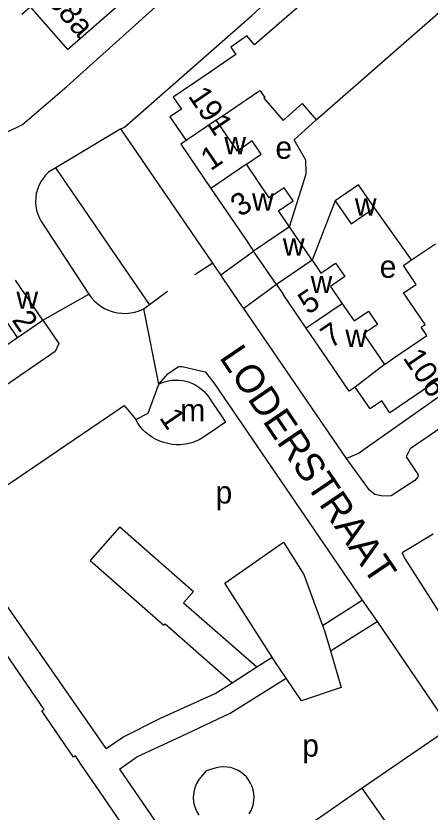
# Model space of a CAD drawing. Extents: x 157569 to 159501, y 382907 to 384670.
# Drawn here: x 158323.4 to 158397.1, y 383704.3 to 383846.2 of the extents above; entities that cross this region are included whole.
import ezdxf

# ---------------------------------------------------------------- set-up
doc = ezdxf.new("R2010")
doc.units = 0
for name, color, linetype in [('BLT_Basislijn', 7, 'Continuous'), ('BLT_Bebouwing', 7, 'Continuous'), ('BLT_Centroide', 7, 'Continuous'), ('BLT_Huisnummer', 7, 'Continuous'), ('BLT_Huisnummer_reeks', 7, 'Continuous'), ('BLT_Onderdoorgang_en_onderverdeling', 7, 'Continuous'), ('BLT_Onderverdeling_panden', 7, 'Continuous'), ('BLT_Straatnaam', 7, 'Continuous'), ('BLT_Vlakafsluiter', 7, 'Continuous')]:
    doc.layers.add(name, color=color, linetype=linetype)

msp = doc.modelspace()

# ---------------------------------------------------------------- linework, layer by layer
at = {"layer": 'BLT_Basislijn'}
for p, q in [((158342.01, 383826.07), (158330.45, 383819.11)), ((158358.4, 383802.12), (158342.01, 383826.07)), ((158330.45, 383819.11), (158329.18, 383818.35)), ((158347.17, 383794.77), (158330.45, 383819.11)), ((158380.22, 383813.28), (158376.1, 383802.66)), ((158393.82, 383802.71), (158387.19, 383811.98)), ((158327.8, 383809.68), (158336.34, 383796.6)), ((158359.82, 383800.05), (158365.69, 383804.29)), ((158358.4, 383802.12), (158355.19, 383800.04)), ((158359.82, 383800.05), (158358.4, 383802.12)), ((158347.17, 383794.77), (158350.37, 383797.15)), ((158369.75, 383798.33), (158363.92, 383794.07)), ((158346.11, 383793.98), (158347.17, 383794.77)), ((158382.24, 383767.34), (158363.92, 383794.07)), ((158339.42, 383715.64), (158311.57, 383755.66)), ((158341.86, 383755.14), (158336.58, 383749.12)), ((158341.86, 383755.14), (158354.97, 383743.62)), ((158336.58, 383749.12), (158349.69, 383737.6)), ((158353.21, 383741.61), (158354.97, 383743.62)), ((158377.93, 383737.58), (158385.04, 383742.09)), ((158385.04, 383742.09), (158387.66, 383738.25)), ((158353.21, 383741.61), (158366.25, 383730.16)), ((158349.69, 383737.6), (158349.91, 383737.85)), ((158349.91, 383737.85), (158361.85, 383727.36)), ((158377.93, 383737.58), (158378.35, 383736.41)), ((158379.35, 383733.05), (158387.66, 383738.25)), ((158387.66, 383738.25), (158400.59, 383719.26)), ((158378.35, 383736.41), (158379.35, 383733.05)), ((158369.47, 383731.13), (158368.98, 383731.89)), ((158371.48, 383728.14), (158369.47, 383731.13)), ((158400.59, 383719.26), (158385.02, 383708.53)), ((158341.8, 383711.96), (158357.3, 383689.41)), ((158385.02, 383708.53), (158357.3, 383689.41)), ((158389.91, 383701.54), (158385.02, 383708.53))]:
    msp.add_line(p, q, dxfattribs=at)
for points in [[(158342.01, 383826.07), (158342.71, 383826.37), (158365.34, 383846.3), (158395.28, 383873.99)], [(158318.74, 383825.56), (158321.24, 383825.28), (158324.51, 383826.85), (158332.42, 383833.63), (158365.06, 383863.02)], [(158372.05, 383808.62), (158375.06, 383818.05), (158374.97, 383820.5), (158372.9, 383824.11), (158376.82, 383827.72)], [(158329.18, 383818.35), (158328.65, 383817.83), (158328.18, 383817.25), (158327.78, 383816.63), (158327.44, 383815.96), (158327.18, 383815.26), (158326.99, 383814.54), (158326.89, 383813.81), (158326.86, 383813.06), (158326.91, 383812.32), (158327.04, 383811.59), (158327.25, 383810.87), (158327.54, 383810.18), (158327.8, 383809.68)], [(158447.4, 383814.83), (158445.1, 383812.79), (158444.97, 383810.48), (158443.72, 383809.2), (158403.65, 383781.83), (158384.34, 383768.23), (158382.24, 383767.34)], [(158445, 383801.93), (158445.32, 383799.37), (158444.41, 383798.79), (158442.06, 383797.45), (158441.26, 383797.32), (158439.12, 383800.11), (158438.87, 383800.08), (158393.56, 383769.02), (158392.87, 383767.64), (158395.01, 383764.4), (158394.93, 383764.04), (158394.38, 383763.41), (158390.15, 383760.66), (158388.71, 383760.59), (158387.28, 383760.91), (158386.32, 383761.7), (158382.24, 383767.34)], [(158363.92, 383794.07), (158363.71, 383794.37), (158360.37, 383799.23), (158359.82, 383800.05)], [(158336.34, 383796.6), (158336.8, 383795.97), (158337.33, 383795.39), (158337.92, 383794.87), (158338.55, 383794.42), (158339.23, 383794.03), (158339.95, 383793.71), (158340.69, 383793.46), (158341.45, 383793.29), (158342.23, 383793.21), (158343.01, 383793.2), (158343.79, 383793.27), (158344.56, 383793.42), (158345.31, 383793.64), (158346.11, 383793.98)], [(158328.13, 383792), (158330.99, 383787.84), (158330.33, 383786.41), (158289.3, 383758.13), (158285.06, 383755.48), (158281.93, 383759.97), (158277.08, 383767.05), (158268.12, 383779.99), (158267.93, 383780.28)], [(158348.79, 383780.59), (158350.39, 383782.44), (158352.33, 383783.75), (158352.94, 383783.74), (158357.03, 383782.8), (158358.62, 383780.8), (158385.04, 383742.09)], [(158311.57, 383755.66), (158342.66, 383776.75), (158344.68, 383774.25)], [(158397.67, 383753.82), (158392.13, 383750.53), (158392.52, 383749.58), (158399.52, 383738.7), (158403.73, 383732.87), (158405.96, 383732.39), (158409.36, 383734.66)], [(158368.98, 383731.89), (158360.55, 383745.11), (158370.98, 383752.4)], [(158370.98, 383752.4), (158374.64, 383746.63), (158377.93, 383737.58)], [(158366.25, 383730.16), (158368.98, 383731.89)], [(158379.35, 383733.05), (158381.28, 383726.53), (158374.19, 383724.12), (158371.48, 383728.14)], [(158361.85, 383727.36), (158366.25, 383730.16)], [(158352.82, 383717.85), (158361.5, 383721.91), (158371.48, 383728.14)], [(158339.42, 383715.64), (158342.39, 383717.66), (158348.97, 383721), (158358.85, 383725.46), (158361.85, 383727.36)], [(158341.8, 383711.96), (158344.87, 383714.13), (158352.82, 383717.85)], [(158365.77, 383706.94), (158365.73, 383707.6), (158365.61, 383708.25), (158365.41, 383708.88), (158365.14, 383709.47), (158364.8, 383710.04), (158364.39, 383710.55), (158363.93, 383711.02), (158363.4, 383711.42), (158362.84, 383711.76), (158362.24, 383712.02), (158361.61, 383712.22), (158360.96, 383712.33), (158360.3, 383712.36), (158359.65, 383712.32), (158359, 383712.19), (158357.24, 383711.62)], [(158357.24, 383711.62), (158356.24, 383710.48), (158355.85, 383709.96), (158355.51, 383709.39), (158355.25, 383708.79), (158355.07, 383708.16), (158354.96, 383707.51), (158354.93, 383706.85), (158354.98, 383706.19), (158355.11, 383705.55), (158355.32, 383704.92), (158355.6, 383704.33), (158355.95, 383703.77)], [(158364.9, 383704), (158365.23, 383704.58), (158365.48, 383705.18), (158365.65, 383705.82), (158365.75, 383706.47), (158365.77, 383706.94)]]:
    msp.add_lwpolyline(points, dxfattribs=at)
at = {"layer": 'BLT_Bebouwing'}
for p, q in [((158376.82, 383827.72), (158407.11, 383854.22)), ((158364.47, 383842.64), (158361.61, 383840.67)), ((158361.37, 383829.25), (158366.79, 383832.94)), ((158374.32, 383830.58), (158376.82, 383827.72)), ((158359.02, 383827.65), (158361.37, 383829.25)), ((158353.65, 383823.99), (158352.7, 383823.34)), ((158352.7, 383823.34), (158358.07, 383815.47)), ((158358.07, 383815.47), (158363.75, 383807.12)), ((158376.1, 383802.66), (158372.05, 383808.62)), ((158369.75, 383798.33), (158365.69, 383804.29)), ((158393.82, 383802.71), (158398.05, 383805.59)), ((158376.1, 383802.66), (158377.37, 383800.81)), ((158328.13, 383792), (158323.28, 383799.09)), ((158369.75, 383798.33), (158371.02, 383796.48)), ((158375.06, 383790.55), (158371.02, 383796.48)), ((158396.24, 383791.21), (158393.56, 383795.14)), ((158323.62, 383788.92), (158328.13, 383792)), ((158378.78, 383785.1), (158375.06, 383790.55)), ((158319.11, 383785.84), (158323.62, 383788.92)), ((158385.27, 383789.53), (158388.97, 383784.1)), ((158390.41, 383785.08), (158396.53, 383789.26)), ((158388.97, 383784.1), (158390.41, 383785.08)), ((158337.59, 383708.98), (158335.06, 383712.68))]:
    msp.add_line(p, q, dxfattribs=at)
for points in [[(158324.42, 383846.54), (158325.91, 383847.84), (158332.56, 383840.24), (158360.35, 383864.6)], [(158378.22, 383851.88), (158365.85, 383841.06), (158364.47, 383842.64)], [(158361.61, 383840.67), (158362.54, 383839.32), (158357.06, 383835.59)], [(158357.06, 383835.59), (158351.37, 383831.72), (158352.82, 383829.6), (158350.78, 383828.21), (158353.65, 383823.99)], [(158366.79, 383832.94), (158367.67, 383831.66), (158367.49, 383831.53), (158370.93, 383827.6), (158374.32, 383830.58)], [(158364.39, 383819.77), (158367.05, 383821.58), (158365.44, 383823.93), (158362.79, 383822.13), (158359.02, 383827.65)], [(158370.11, 383811.46), (158372.74, 383813.24), (158371.14, 383815.59), (158368.48, 383813.78), (158364.39, 383819.77)], [(158387.19, 383811.98), (158384.37, 383816.11), (158380.22, 383813.28)], [(158380.22, 383813.28), (158383.04, 383809.15), (158387.19, 383811.98)], [(158372.05, 383808.62), (158370.4, 383811.04), (158370.11, 383811.46)], [(158363.75, 383807.12), (158364.04, 383806.71), (158365.69, 383804.29)], [(158377.37, 383800.81), (158377.66, 383800.37), (158380.29, 383802.16), (158381.94, 383799.75), (158379.36, 383797.99), (158381.46, 383794.92)], [(158393.56, 383795.14), (158392.4, 383796.84), (158394.65, 383798.37), (158392.37, 383801.72), (158393.82, 383802.71)], [(158381.46, 383794.92), (158383.56, 383791.84), (158386.14, 383793.6), (158387.76, 383791.23), (158385.27, 383789.53)], [(158396.53, 383789.26), (158395.53, 383790.73), (158396.24, 383791.21)], [(158383.75, 383780.05), (158382.71, 383779.34), (158378.78, 383785.1)], [(158400.49, 383784.46), (158401.31, 383783.25), (158394.73, 383778.76)], [(158348.79, 383780.59), (158349.29, 383780.81), (158349.88, 383781.02), (158350.49, 383781.17), (158351.12, 383781.27), (158351.75, 383781.31), (158352.38, 383781.29), (158353.01, 383781.22), (158353.38, 383781.15), (158353.62, 383781.09), (158354.23, 383780.91), (158354.82, 383780.68), (158355.38, 383780.39), (158355.91, 383780.05), (158356.41, 383779.67), (158356.88, 383779.24), (158357.31, 383778.78), (158357.69, 383778.28), (158358.48, 383777.08), (158359.88, 383774.97), (158360.66, 383773.79), (158359.36, 383772.9), (158358.98, 383772.64), (158356.96, 383771.26), (158356.75, 383771.11), (158355.98, 383770.67), (158355.57, 383770.47), (158354.87, 383770.2), (158354.14, 383770), (158353.48, 383769.87), (158352.65, 383769.78), (158351.9, 383769.78), (158351.15, 383769.84), (158350.4, 383769.97), (158349.67, 383770.16), (158348.96, 383770.42), (158348.33, 383770.7), (158347.68, 383771.06), (158347.07, 383771.47), (158346.5, 383771.93), (158345.97, 383772.45), (158345.49, 383773.01), (158345.06, 383773.61), (158344.68, 383774.25)], [(158344.68, 383774.25), (158346.89, 383775.42), (158348.79, 383780.59)], [(158394.73, 383778.76), (158389.93, 383775.49), (158388.5, 383777.58), (158386.41, 383776.15), (158383.75, 383780.05)], [(158335.06, 383712.68), (158333.94, 383714.31), (158333.61, 383714.09), (158327.97, 383722.32), (158328.37, 383722.6), (158321.55, 383732.57)], [(158342.99, 383701.1), (158337.59, 383708.98)]]:
    msp.add_lwpolyline(points, dxfattribs=at)
at = {"layer": 'BLT_Onderdoorgang_en_onderverdeling'}
for p, q in [((158372.05, 383808.62), (158365.69, 383804.29)), ((158376.1, 383802.66), (158369.75, 383798.33))]:
    msp.add_line(p, q, dxfattribs=at)
at = {"layer": 'BLT_Onderverdeling_panden'}
for p, q in [((158359.02, 383827.65), (158353.65, 383823.99)), ((158364.39, 383819.77), (158358.07, 383815.47)), ((158323.62, 383788.92), (158318.78, 383796.01)), ((158381.46, 383794.92), (158375.06, 383790.55)), ((158388.97, 383784.1), (158383.75, 383780.05))]:
    msp.add_line(p, q, dxfattribs=at)
at = {"layer": 'BLT_Vlakafsluiter'}
for p, q in [((158328.13, 383792), (158336.34, 383796.6)), ((158348.79, 383780.59), (158346.11, 383793.98))]:
    msp.add_line(p, q, dxfattribs=at)

# ---------------------------------------------------------------- texts
at = {"layer": 'BLT_Centroide'}
for s, p in [('w', (158360.47, 383821.56)), ('e', (158369.57, 383820.75)), ('w', (158365.41, 383811.5)), ('w', (158383.71, 383810.62)), ('w', (158370.89, 383803.47)), ('e', (158388.13, 383799.53)), ('w', (158375.84, 383796.8)), ('w', (158323.45, 383794.02)), ('w', (158382.02, 383787.22)), ('m', (158352.62, 383773.94)), ('p', (158358.9, 383759.3)), ('p', (158374.34, 383714.18))]:
    msp.add_text(s, height=4, dxfattribs=at).set_placement(p)
at = {"layer": 'BLT_Huisnummer'}
for s, rotation, p in [('1', 34.2613, (158358.03, 383818.51)), ('3', 34.2536, (158363.32, 383810.26)), ('5', 34.2974, (158375.38, 383792.87)), ('2', 304.3563, (158322.52, 383792.02)), ('7', 34.2929, (158379.4, 383786.86)), ('1', 304.3462, (158348.79, 383774.6))]:
    msp.add_text(s, height=4, rotation=rotation, dxfattribs=at).set_placement(p)
at = {"layer": 'BLT_Huisnummer_reeks'}
for s, rotation, p in [('68a', 311.2128, (158328.73, 383848.83)), ('191', 304.2622, (158353.91, 383831.93)), ('106', 304.2922, (158392.16, 383785.25))]:
    msp.add_text(s, height=4, rotation=rotation, dxfattribs=at).set_placement(p)
at = {"layer": 'BLT_Straatnaam'}
msp.add_text('LODERSTRAAT', height=5, rotation=304.2143, dxfattribs=at).set_placement((158359.45, 383785.34))

doc.saveas('drawing.dxf')
